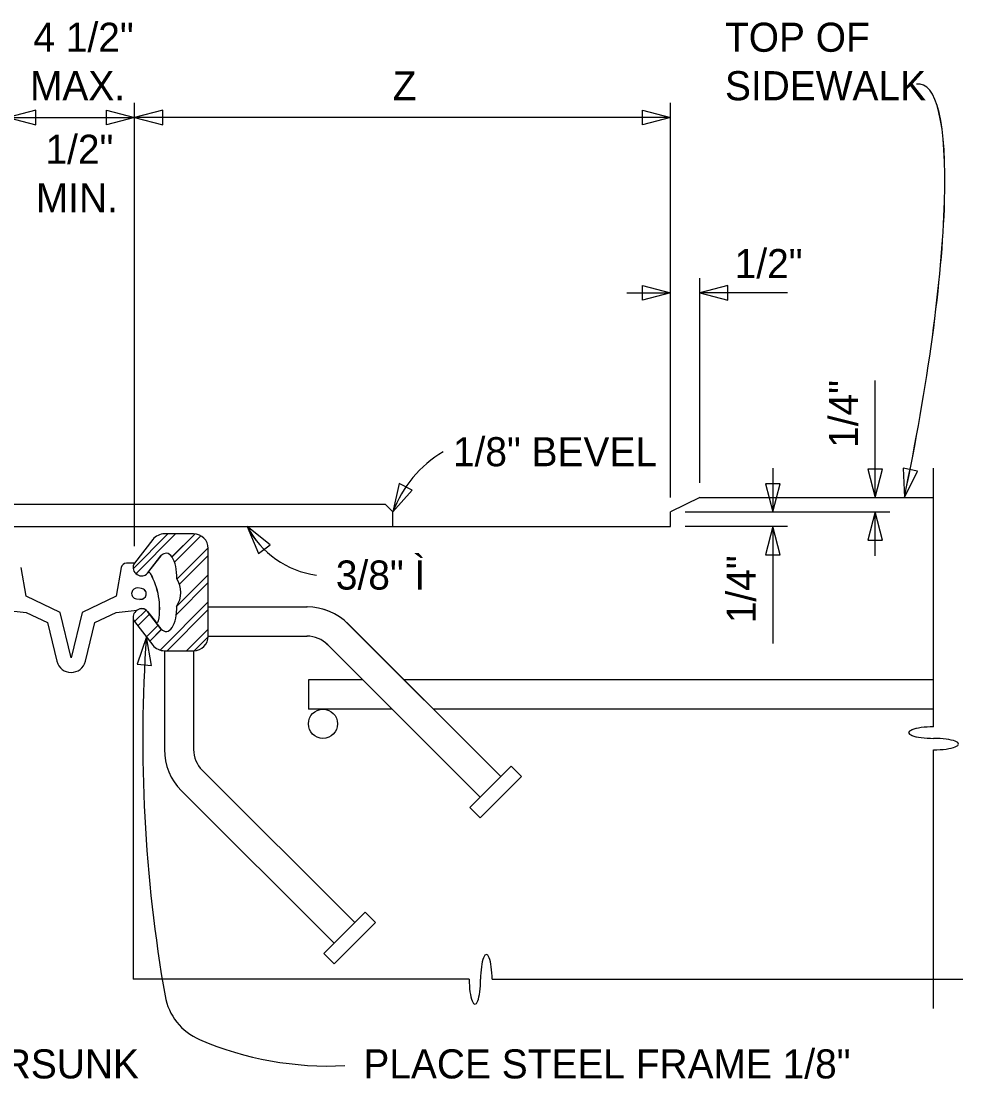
# Model space of a CAD drawing. Extents: x 19590 to 20151, y 19944 to 20103.
# Drawn here: x 19891.62 to 19907.73, y 20061.56 to 20079.66 of the extents above; entities that cross this region are included whole.
import ezdxf

# ---------------------------------------------------------------- set-up
doc = ezdxf.new("R2010")
doc.units = 0
for name, color, linetype in [('DETAIL_PR', 7, 'Continuous'), ('Level 1', 7, 'Continuous'), ('MT_PAVT_MRKGS_EX', 7, 'Continuous'), ('MT_PAVT_MRKGS_EX_REF', 7, 'Continuous'), ('PAVT_MRKGS_QUANT', 7, 'Continuous')]:
    doc.layers.add(name, color=color, linetype=linetype)

# ---------------------------------------------------------------- blocks, each defined once
blk = doc.blocks.new('BRE')
at = {"layer": 'DETAIL_PR'}
for centre, ratio, start_param, end_param in [((0, 0.098), 0.230206, 4.712389, 7.853982), ((0, -0.098), 0.230204, 1.570796, 4.712389)]:
    blk.add_ellipse(centre, major_axis=(-0.427, 0), ratio=ratio, start_param=start_param, end_param=end_param, dxfattribs=at)
blk = doc.blocks.new('EJ3H')
at = {"layer": 'MT_PAVT_MRKGS_EX'}
for p, q in [((91.609, -24.597), (91.109, -24.847)), ((91.609, -24.597), (95.609, -24.597)), ((86.234, -24.722), (73.859, -24.722)), ((86.359, -24.847), (86.234, -24.722)), ((86.359, -25.097), (86.359, -24.847)), ((91.109, -25.097), (91.109, -24.847)), ((73.859, -25.097), (86.359, -25.097)), ((82.867, -25.097), (91.109, -25.097)), ((82.508, -25.222), (81.913, -25.818)), ((82.252, -25.319), (81.938, -25.722)), ((82.641, -25.222), (81.963, -25.9)), ((82.949, -25.222), (82.449, -25.222)), ((82.973, -25.222), (82.578, -25.616)), ((83.072, -25.255), (82.623, -25.705)), ((83.199, -25.46), (82.663, -25.996)), ((83.199, -26.972), (83.199, -25.472)), ((82.16, -25.895), (82.39, -25.599)), ((83.199, -25.593), (82.707, -26.085)), ((80.082, -26.288), (79.997, -25.8)), ((81.708, -25.8), (81.624, -26.288)), ((81.938, -25.722), (81.801, -25.722)), ((81.985, -25.917), (81.96, -25.898)), ((81.96, -25.898), (81.985, -25.917)), ((83.199, -26.054), (82.655, -26.599)), ((83.199, -25.922), (82.66, -26.461)), ((82.055, -26.157), (81.993, -26.148)), ((80.665, -26.565), (80.082, -26.288)), ((81.624, -26.288), (81.041, -26.565)), ((81.969, -26.334), (82.031, -26.342)), ((83.199, -26.386), (82.374, -27.211)), ((79.721, -26.528), (80.082, -26.565)), ((80.082, -26.565), (80.45, -26.74)), ((80.853, -27.344), (80.665, -26.565)), ((81.041, -26.565), (80.853, -27.344)), ((81.256, -26.74), (81.624, -26.565)), ((81.624, -26.565), (81.985, -26.528)), ((82.134, -26.525), (81.937, -26.722)), ((81.985, -26.528), (81.96, -26.547)), ((82.196, -26.596), (81.995, -26.796)), ((82.16, -26.55), (82.293, -26.721)), ((82.39, -26.846), (82.16, -26.55)), ((83.199, -26.518), (82.495, -27.222)), ((83.199, -26.472), (84.888, -26.472)), ((80.45, -26.74), (80.61, -27.403)), ((81.096, -27.403), (81.256, -26.74)), ((81.912, -26.652), (81.912, -32.844)), ((81.938, -26.722), (82.252, -27.126)), ((82.341, -26.782), (82.14, -26.983)), ((85.595, -26.765), (88.204, -29.374)), ((82.398, -26.856), (82.197, -27.056)), ((83.199, -26.85), (82.826, -27.222)), ((83.199, -26.982), (82.959, -27.222)), ((83.199, -26.972), (84.888, -26.972)), ((85.242, -27.119), (87.851, -29.728)), ((82.449, -27.222), (82.949, -27.222)), ((82.449, -27.222), (82.449, -28.912)), ((82.949, -27.222), (82.949, -28.912)), ((85.845, -27.722), (84.912, -27.722)), ((84.912, -27.722), (84.912, -28.222)), ((95.609, -27.722), (86.552, -27.722)), ((86.345, -28.222), (84.912, -28.222)), ((95.609, -28.222), (87.052, -28.222)), ((83.095, -29.265), (85.704, -31.874)), ((88.381, -29.197), (87.674, -29.904)), ((88.381, -29.197), (88.558, -29.374)), ((88.558, -29.374), (87.851, -30.081)), ((82.742, -29.619), (85.351, -32.228)), ((87.674, -29.904), (87.851, -30.081)), ((85.881, -31.697), (85.174, -32.404)), ((85.881, -31.697), (86.058, -31.874)), ((86.058, -31.874), (85.351, -32.581)), ((85.174, -32.404), (85.351, -32.581))]:
    blk.add_line(p, q, dxfattribs=at)
blk.add_circle((85.162, -28.472), 0.25, dxfattribs=at)
for centre, radius, start, end in [((82.449, -25.472), 0.25, 90, 142.143), ((82.949, -25.472), 0.25, 0, 90), ((81.801, -25.816), 0.0938, 90, 170.2238), ((82.037, -25.799), 0.125, 142.143, 232.143), ((82.037, -25.799), 0.125, 142.143, 232.143), ((82.061, -25.818), 0.125, 232.143, 322.143), ((82.061, -25.818), 0.125, 232.143, 321.3779), ((82.183, -25.916), 0.0312, 29.2634, 141.3779), ((81.143, -26.499), 1.224, 350.1703, 29.2634), ((82.311, -26.222), 0.419, 325.0258, 33.6795), ((81.981, -26.241), 0.0937, 170.2238, 262.4005), ((81.981, -26.241), 0.0938, 82.4005, 170.2238), ((82.043, -26.25), 0.0938, 350.2238, 82.4005), ((82.043, -26.25), 0.0938, 262.4005, 350.2238), ((82.037, -26.646), 0.125, 127.857, 217.857), ((82.061, -26.627), 0.125, 37.857, 127.857), ((82.061, -26.627), 0.125, 37.857, 127.857), ((84.888, -27.472), 1, 45, 90), ((82.318, -26.702), 0.0312, 217.857, 350.1703), ((82.449, -26.972), 0.25, 217.857, 270), ((82.949, -26.972), 0.25, 270, 360), ((84.888, -27.472), 0.5, 45, 90), ((80.853, -27.344), 0.25, 193.5864, 346.4136), ((83.449, -28.912), 1, 180, 225), ((83.449, -28.912), 0.5, 180, 225)]:
    blk.add_arc(centre, radius, start, end, dxfattribs=at)
for centre, major_axis, start_param, end_param in [((82.466, -25.979), (-0.016, -0.425), 1.562431, 3.622562), ((82.466, -26.466), (0.016, -0.425), 5.802216, 7.862347)]:
    blk.add_ellipse(centre, major_axis=major_axis, ratio=0.457019, start_param=start_param, end_param=end_param, dxfattribs=at)
at = {"layer": 'MT_PAVT_MRKGS_EX_REF'}
for p, q in [((81.938, -25.43), (81.938, -17.847)), ((91.109, -24.597), (91.109, -17.847)), ((80.249, -17.973), (79.768, -18.097)), ((79.768, -18.097), (81.938, -18.097)), ((79.768, -18.097), (80.249, -18.222)), ((80.249, -18.222), (80.249, -17.973)), ((81.456, -17.973), (81.938, -18.097)), ((81.456, -18.222), (81.456, -17.973)), ((81.938, -18.097), (81.456, -18.222)), ((82.42, -17.973), (81.938, -18.097)), ((91.109, -18.097), (81.938, -18.097)), ((81.938, -18.097), (82.42, -18.222)), ((82.42, -18.222), (82.42, -17.973)), ((90.627, -17.973), (91.109, -18.097)), ((90.627, -18.222), (90.627, -17.973)), ((91.109, -18.097), (90.627, -18.222)), ((90.627, -20.973), (91.109, -21.097)), ((90.627, -21.222), (90.627, -20.973)), ((91.609, -24.347), (91.609, -20.847)), ((92.091, -20.973), (91.609, -21.097)), ((92.091, -21.222), (92.091, -20.973)), ((91.109, -21.097), (90.627, -21.222)), ((91.609, -21.097), (92.091, -21.222)), ((94.485, -24.116), (94.609, -24.597)), ((94.734, -24.116), (94.485, -24.116)), ((94.609, -24.597), (94.734, -24.116)), ((95.088, -24.1), (95.109, -24.597)), ((95.331, -24.152), (95.088, -24.1)), ((95.109, -24.597), (95.331, -24.152)), ((95.609, -27.524), (95.609, -24.097)), ((95.609, -28.524), (95.609, -24.097)), ((86.467, -24.361), (86.359, -24.847)), ((86.688, -24.474), (86.467, -24.361)), ((92.735, -24.366), (92.859, -24.847)), ((92.984, -24.366), (92.735, -24.366)), ((92.859, -24.847), (92.984, -24.366)), ((86.359, -24.847), (86.688, -24.474)), ((91.359, -24.847), (94.859, -24.847)), ((94.609, -24.847), (94.485, -25.329)), ((94.734, -25.329), (94.609, -24.847)), ((84.257, -25.407), (83.867, -25.097)), ((83.867, -25.097), (84.058, -25.557)), ((93.109, -25.097), (91.359, -25.097)), ((92.859, -25.097), (92.735, -25.579)), ((92.984, -25.579), (92.859, -25.097)), ((94.485, -25.329), (94.734, -25.329)), ((84.058, -25.557), (84.257, -25.407)), ((92.735, -25.579), (92.984, -25.579)), ((82.14, -26.983), (81.981, -27.454)), ((82.229, -27.472), (82.14, -26.983)), ((81.981, -27.454), (82.229, -27.472)), ((95.609, -33.344), (95.609, -28.917)), ((87.663, -32.844), (81.912, -32.844)), ((88.056, -32.844), (96.109, -32.844))]:
    blk.add_line(p, q, dxfattribs=at)
for centre, radius, start, end in [((107.491, -28.746), 25.412, 176.0213, 189.9305), ((83.445, -32.956), 1, 189.9305, 246.7533), ((85.255, -28.742), 5.586, 246.7533, 272.8645)]:
    blk.add_arc(centre, radius, start, end, dxfattribs=at)
at = {"layer": 'PAVT_MRKGS_QUANT'}
for p, q in [((90.359, -21.097), (91.109, -21.097)), ((93.109, -21.097), (91.609, -21.097)), ((94.609, -24.597), (94.609, -22.597)), ((92.859, -24.097), (92.859, -24.847)), ((94.609, -25.597), (94.609, -24.847)), ((92.859, -25.097), (92.859, -27.097))]:
    blk.add_line(p, q, dxfattribs=at)
for centre, radius, start, end in [((88.254, -25.552), 2.022, 120.8358, 159.6044), ((85.255, -24.374), 1.566, 207.5156, 262.4161)]:
    blk.add_arc(centre, radius, start, end, dxfattribs=at)
blk.add_ellipse((93.904, -24.477), major_axis=(1.489, 6.95), ratio=0.169331, start_param=4.731306, end_param=6.346137, dxfattribs=at)
for p, rotation in [((95.609, -28.721), 180), ((87.859, -32.844), 90)]:
    blk.add_blockref('BRE', p, dxfattribs=dict(at, rotation=rotation))
at = {"layer": 'Level 1'}
blk.add_text('3/8" Ì', height=0.4976, dxfattribs=at).set_placement((85.382, -26.175))
at = {"layer": 'MT_PAVT_MRKGS_EX_REF'}
for s, height, p in [('4 1/2"', 0.4976, (80.207, -16.973)), ('TOP OF', 0.4976, (92.04, -16.973)), ('MAX.', 0.4976, (80.149, -17.803)), ('Z', 0.498, (86.354, -17.805)), ('SIDEWALK', 0.4976, (92.04, -17.803)), ('1/2"', 0.4976, (80.414, -18.89)), ('MIN.', 0.4976, (80.249, -19.719)), ('1/8" BEVEL', 0.4976, (87.385, -24.065)), ('PLACE STEEL FRAME 1/8" ', 0.49762, (85.853, -34.54)), ('FLATHEAD COUNTERSUNK', 0.49762, (73.213, -34.54))]:
    blk.add_text(s, height=height, dxfattribs=at).set_placement(p)
for s, rotation, p in [('1/2"', 360, (92.206, -20.846)), ('1/4"', 90, (94.316, -23.751)), ('1/4"', 90, (92.566, -26.751))]:
    blk.add_text(s, height=0.4976, rotation=rotation, dxfattribs=at).set_placement(p)

msp = doc.modelspace()

# ---------------------------------------------------------------- linework, layer by layer
at = {"layer": 'MT_PAVT_MRKGS_EX'}
for p, q in [((19897.858, 20071.384), (19885.483, 20071.384)), ((19897.983, 20071.259), (19897.858, 20071.384)), ((19903.233, 20071.509), (19902.733, 20071.259)), ((19903.233, 20071.509), (19907.233, 20071.509)), ((19897.983, 20071.009), (19897.983, 20071.259)), ((19902.733, 20071.009), (19902.733, 20071.259)), ((19885.483, 20071.009), (19897.983, 20071.009)), ((19894.491, 20071.009), (19902.733, 20071.009)), ((19894.133, 20070.884), (19893.537, 20070.288)), ((19894.265, 20070.884), (19893.587, 20070.206)), ((19894.573, 20070.884), (19894.073, 20070.884)), ((19894.597, 20070.884), (19894.203, 20070.49)), ((19894.697, 20070.851), (19894.247, 20070.401)), ((19893.876, 20070.787), (19893.562, 20070.384)), ((19894.823, 20070.646), (19894.288, 20070.111)), ((19893.784, 20070.211), (19894.015, 20070.508)), ((19894.823, 20070.513), (19894.331, 20070.021)), ((19894.823, 20069.134), (19894.823, 20070.634)), ((19891.706, 20069.818), (19891.622, 20070.306)), ((19893.332, 20070.306), (19893.248, 20069.818)), ((19893.562, 20070.384), (19893.425, 20070.384)), ((19893.609, 20070.189), (19893.584, 20070.208)), ((19893.584, 20070.208), (19893.609, 20070.189)), ((19894.823, 20070.184), (19894.284, 20069.646)), ((19893.68, 20069.95), (19893.618, 20069.958)), ((19894.823, 20070.052), (19894.279, 20069.507)), ((19892.289, 20069.541), (19891.706, 20069.818)), ((19893.248, 20069.818), (19892.665, 20069.541)), ((19893.593, 20069.772), (19893.655, 20069.764)), ((19891.345, 20069.578), (19891.706, 20069.541)), ((19893.248, 20069.541), (19893.609, 20069.578)), ((19893.758, 20069.581), (19893.562, 20069.384)), ((19893.609, 20069.578), (19893.584, 20069.559)), ((19894.823, 20069.72), (19893.998, 20068.895)), ((19894.823, 20069.588), (19894.119, 20068.884)), ((19894.823, 20069.634), (19896.513, 20069.634)), ((19891.706, 20069.541), (19892.074, 20069.366)), ((19892.477, 20068.762), (19892.289, 20069.541)), ((19892.665, 20069.541), (19892.477, 20068.762)), ((19892.88, 20069.366), (19893.248, 20069.541)), ((19893.536, 20069.454), (19893.536, 20063.262)), ((19893.562, 20069.384), (19893.876, 20068.98)), ((19893.82, 20069.51), (19893.62, 20069.31)), ((19893.784, 20069.556), (19893.918, 20069.385)), ((19894.015, 20069.26), (19893.784, 20069.556)), ((19892.074, 20069.366), (19892.234, 20068.703)), ((19892.72, 20068.703), (19892.88, 20069.366)), ((19893.965, 20069.324), (19893.765, 20069.123)), ((19894.022, 20069.251), (19893.822, 20069.05)), ((19894.823, 20069.256), (19894.451, 20068.884)), ((19897.22, 20069.341), (19899.828, 20066.732)), ((19894.823, 20069.124), (19894.583, 20068.884)), ((19894.823, 20069.134), (19896.513, 20069.134)), ((19894.073, 20068.884), (19894.573, 20068.884)), ((19894.073, 20068.884), (19894.073, 20067.194)), ((19894.573, 20068.884), (19894.573, 20067.194)), ((19896.866, 20068.987), (19899.475, 20066.378)), ((19897.47, 20068.384), (19896.536, 20068.384)), ((19896.536, 20068.384), (19896.536, 20067.884)), ((19907.233, 20068.384), (19898.177, 20068.384)), ((19897.97, 20067.884), (19896.536, 20067.884)), ((19907.233, 20067.884), (19898.677, 20067.884)), ((19900.005, 20066.909), (19899.298, 20066.202)), ((19900.005, 20066.909), (19900.182, 20066.732)), ((19894.72, 20066.841), (19897.328, 20064.232)), ((19900.182, 20066.732), (19899.475, 20066.025)), ((19894.366, 20066.487), (19896.975, 20063.878)), ((19899.298, 20066.202), (19899.475, 20066.025)), ((19897.505, 20064.409), (19896.798, 20063.702)), ((19897.505, 20064.409), (19897.682, 20064.232)), ((19897.682, 20064.232), (19896.975, 20063.525)), ((19896.798, 20063.702), (19896.975, 20063.525))]:
    msp.add_line(p, q, dxfattribs=at)
msp.add_circle((19896.786, 20067.634), 0.25, dxfattribs=at)
for centre, radius, start, end in [((19894.073, 20070.634), 0.25, 90, 142.143), ((19894.573, 20070.634), 0.25, 0, 90), ((19893.425, 20070.29), 0.0938, 90, 170.2238), ((19893.661, 20070.307), 0.125, 142.143, 232.143), ((19893.661, 20070.307), 0.125, 142.143, 232.143), ((19893.686, 20070.288), 0.125, 232.143, 322.143), ((19893.686, 20070.288), 0.125, 232.143, 321.3779), ((19893.808, 20070.19), 0.0312, 29.2634, 141.3779), ((19892.768, 20069.607), 1.224, 350.1703, 29.2634), ((19893.935, 20069.884), 0.419, 325.0258, 33.6795), ((19893.605, 20069.865), 0.0938, 82.4005, 170.2238), ((19893.667, 20069.857), 0.0938, 350.2238, 82.4005), ((19893.605, 20069.865), 0.0937, 170.2238, 262.4005), ((19893.667, 20069.857), 0.0938, 262.4005, 350.2238), ((19893.661, 20069.46), 0.125, 127.857, 217.857), ((19893.686, 20069.48), 0.125, 37.857, 127.857), ((19893.686, 20069.48), 0.125, 37.857, 127.857), ((19896.513, 20068.634), 1, 45, 90), ((19893.942, 20069.404), 0.0312, 217.857, 350.1703), ((19894.573, 20069.134), 0.25, 270, 360), ((19896.513, 20068.634), 0.5, 45, 90), ((19894.073, 20069.134), 0.25, 217.857, 270), ((19892.477, 20068.762), 0.25, 193.5864, 346.4136), ((19895.073, 20067.194), 1, 180, 225), ((19895.073, 20067.194), 0.5, 180, 225)]:
    msp.add_arc(centre, radius, start, end, dxfattribs=at)
for centre, major_axis, start_param, end_param in [((19894.09, 20070.127), (-0.016, -0.425), 1.562431, 3.622562), ((19894.09, 20069.64), (0.016, -0.425), 5.802216, 7.862347)]:
    msp.add_ellipse(centre, major_axis=major_axis, ratio=0.457019, start_param=start_param, end_param=end_param, dxfattribs=at)
at = {"layer": 'MT_PAVT_MRKGS_EX_REF'}
for p, q in [((19893.562, 20070.676), (19893.562, 20078.259)), ((19902.733, 20071.509), (19902.733, 20078.259)), ((19891.874, 20078.133), (19891.392, 20078.009)), ((19891.874, 20077.884), (19891.874, 20078.133)), ((19893.08, 20078.133), (19893.562, 20078.009)), ((19893.08, 20077.884), (19893.08, 20078.133)), ((19894.044, 20078.133), (19893.562, 20078.009)), ((19894.044, 20077.884), (19894.044, 20078.133)), ((19902.252, 20078.133), (19902.733, 20078.009)), ((19902.252, 20077.884), (19902.252, 20078.133)), ((19891.392, 20078.009), (19893.562, 20078.009)), ((19891.392, 20078.009), (19891.874, 20077.884)), ((19893.562, 20078.009), (19893.08, 20077.884)), ((19902.733, 20078.009), (19893.562, 20078.009)), ((19893.562, 20078.009), (19894.044, 20077.884)), ((19902.733, 20078.009), (19902.252, 20077.884)), ((19903.233, 20071.759), (19903.233, 20075.259)), ((19902.252, 20075.133), (19902.733, 20075.009)), ((19902.252, 20074.884), (19902.252, 20075.133)), ((19902.733, 20075.009), (19902.252, 20074.884)), ((19903.715, 20075.133), (19903.233, 20075.009)), ((19903.233, 20075.009), (19903.715, 20074.884)), ((19903.715, 20074.884), (19903.715, 20075.133)), ((19906.109, 20071.991), (19906.233, 20071.509)), ((19906.358, 20071.991), (19906.109, 20071.991)), ((19906.233, 20071.509), (19906.358, 20071.991)), ((19906.712, 20072.006), (19906.733, 20071.509)), ((19906.955, 20071.954), (19906.712, 20072.006)), ((19906.733, 20071.509), (19906.955, 20071.954)), ((19907.233, 20068.582), (19907.233, 20072.009)), ((19907.233, 20067.582), (19907.233, 20072.009)), ((19898.091, 20071.745), (19897.983, 20071.259)), ((19898.313, 20071.632), (19898.091, 20071.745)), ((19904.359, 20071.741), (19904.483, 20071.259)), ((19904.608, 20071.741), (19904.359, 20071.741)), ((19904.483, 20071.259), (19904.608, 20071.741)), ((19897.983, 20071.259), (19898.313, 20071.632)), ((19902.983, 20071.259), (19906.483, 20071.259)), ((19906.233, 20071.259), (19906.109, 20070.777)), ((19906.358, 20070.777), (19906.233, 20071.259)), ((19895.881, 20070.699), (19895.491, 20071.009)), ((19895.491, 20071.009), (19895.682, 20070.549)), ((19904.733, 20071.009), (19902.983, 20071.009)), ((19904.483, 20071.009), (19904.359, 20070.527)), ((19904.608, 20070.527), (19904.483, 20071.009)), ((19895.682, 20070.549), (19895.881, 20070.699)), ((19906.109, 20070.777), (19906.358, 20070.777)), ((19904.359, 20070.527), (19904.608, 20070.527)), ((19893.765, 20069.123), (19893.606, 20068.652)), ((19893.854, 20068.634), (19893.765, 20069.123)), ((19893.606, 20068.652), (19893.854, 20068.634)), ((19907.233, 20062.762), (19907.233, 20067.189)), ((19899.287, 20063.262), (19893.536, 20063.262)), ((19899.68, 20063.262), (19907.733, 20063.262))]:
    msp.add_line(p, q, dxfattribs=at)
for centre, radius, start, end in [((19919.115, 20067.36), 25.412, 176.0213, 189.9305), ((19895.069, 20063.15), 1, 189.9305, 246.7533), ((19896.879, 20067.364), 5.586, 246.7533, 272.8645)]:
    msp.add_arc(centre, radius, start, end, dxfattribs=at)
at = {"layer": 'PAVT_MRKGS_QUANT'}
for p, q in [((19901.983, 20075.009), (19902.733, 20075.009)), ((19904.733, 20075.009), (19903.233, 20075.009)), ((19906.233, 20071.509), (19906.233, 20073.509)), ((19904.483, 20072.009), (19904.483, 20071.259)), ((19906.233, 20070.509), (19906.233, 20071.259)), ((19904.483, 20071.009), (19904.483, 20069.009))]:
    msp.add_line(p, q, dxfattribs=at)
for centre, radius, start, end in [((19899.879, 20070.554), 2.022, 120.8358, 159.6044), ((19896.88, 20071.732), 1.566, 207.5156, 262.4161)]:
    msp.add_arc(centre, radius, start, end, dxfattribs=at)
msp.add_ellipse((19905.529, 20071.629), major_axis=(1.489, 6.95), ratio=0.169331, start_param=4.731306, end_param=6.346137, dxfattribs=at)

# ---------------------------------------------------------------- block references
at = {"layer": 'Level 1'}
msp.add_blockref('EJ3H', (19811.624, 20096.106), dxfattribs=at)
at = {"layer": 'PAVT_MRKGS_QUANT'}
for p, rotation in [((19907.234, 20067.385), 180), ((19899.483, 20063.262), 90)]:
    msp.add_blockref('BRE', p, dxfattribs=dict(at, rotation=rotation))

# ---------------------------------------------------------------- texts
at = {"layer": 'Level 1'}
msp.add_text('3/8" Ì', height=0.4976, dxfattribs=at).set_placement((19897.006, 20069.931))
at = {"layer": 'MT_PAVT_MRKGS_EX_REF'}
for s, height, p in [('4 1/2"', 0.4976, (19891.831, 20079.133)), ('TOP OF', 0.4976, (19903.664, 20079.133)), ('MAX.', 0.4976, (19891.773, 20078.304)), ('Z', 0.498, (19897.978, 20078.302)), ('SIDEWALK', 0.4976, (19903.664, 20078.304)), ('1/2"', 0.4976, (19892.038, 20077.216)), ('MIN.', 0.4976, (19891.873, 20076.387)), ('1/8" BEVEL', 0.4976, (19899.009, 20072.041)), ('FLATHEAD COUNTERSUNK', 0.49762, (19884.838, 20061.566)), ('PLACE STEEL FRAME 1/8" ', 0.49762, (19897.477, 20061.566))]:
    msp.add_text(s, height=height, dxfattribs=at).set_placement(p)
for s, rotation, p in [('1/2"', 360, (19903.83, 20075.26)), ('1/4"', 90, (19905.941, 20072.355)), ('1/4"', 90, (19904.191, 20069.355))]:
    msp.add_text(s, height=0.4976, rotation=rotation, dxfattribs=at).set_placement(p)

doc.saveas('drawing.dxf')
